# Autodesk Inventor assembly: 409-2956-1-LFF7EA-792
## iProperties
Created: 2010-09
Part Number: 409-2956-1-LFF7EA-792
Document SubType Name: Weldment
Designer: S. Boerckel
Weld Material: Welded Aluminum-6061
Mass: 5511.57 g
Surface Area: 2303.77 cm^2
Volume: 698.903 cm^3
Density: 7.88603 g/cm^3
Description: 2" PIPE STAND
Material: WELDMENT
SMR: =<MATERIAL>
Author: S. Boerckel
Revision Number: A
